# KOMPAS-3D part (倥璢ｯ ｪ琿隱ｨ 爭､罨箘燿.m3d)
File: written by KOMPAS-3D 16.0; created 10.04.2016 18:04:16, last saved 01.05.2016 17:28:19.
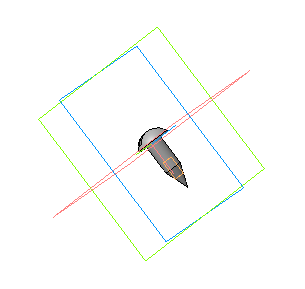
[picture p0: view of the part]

Referenced files in E:\Libs\PartLib\DATA\vault\Methods\Kompas\3D\: PLib_Screw_Shurup_900.m3d
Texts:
  Л63 ГОСТ 15527-2004
  Шуруп 1-5x16.3 ГОСТ 1144-80
  head2
  head4
  groove1
  fillet4
  head3
  groove4
  head5
  fillet1
  groove2
  groove3
  fillet2
  groove5
  head1
  (-) Шуруп 1-5x16.3 ГОСТ 1144-80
